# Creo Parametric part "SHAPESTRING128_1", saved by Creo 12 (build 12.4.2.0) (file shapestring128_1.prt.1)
Units: Custom; MM, KILOGRAM, SECS

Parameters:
  PTC_WM_ITERATION = "0"
  PTC_WM_VERSION = "-.0"
  PTC_WM_LIFECYCLE_STATE = "In Work"
  PTC_WM_LIFECYCLE = "MO_CADDocument"
  PTC_WM_CREATED_BY = "Maximilian Roepper (Z0017RMS: MO)"
  PTC_WM_CREATED_ON = "18-Sep-26 11:36:42 AM"
  PTC_WM_MODIFIED_BY = "Maximilian Roepper (Z0017RMS: MO)"
  PTC_WM_MODIFIED_ON = "18-Sep-26 11:36:46 AM"
  PDMLINKNUMBER = "PDM000071454796"
  PTC_WM_NAME = "shapestring128_1.prt"
  PTC_WM_NUMBER = "PDM000071454796"

Other parameters: WEIGHT, WEIGHT_FACTOR, WEIGHT_ADD, _MASS_TEMP, _DIFF_TEMP, MC_ERRORS, SUPPLIER

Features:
  1. coordinate system
  2. datum plane "PRT_YZ"
  3. datum plane "PRT_XY"
  4. datum plane "PRT_XZ"
  5. coordinate system
  6. datum axis
  7. datum axis
  8. datum axis
  9. coordinate system
  10. imported feature

Other named items: PRT, SIEMENS_MO, DRW_VIEW_ORG, PRT_X, PRT_Y, PRT_Z, CS0, ROUGH_GROB

Layers: 00_STD_CSYS-KSYS, 01_STD_PLANES-EBENEN, 02_STD_AXES-ACHSEN, 03_STD_CSYS-KSYS, 24_IMPORT_FEAT-IMPORT_KE, INTFCLR

Surfaces: 1 plane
